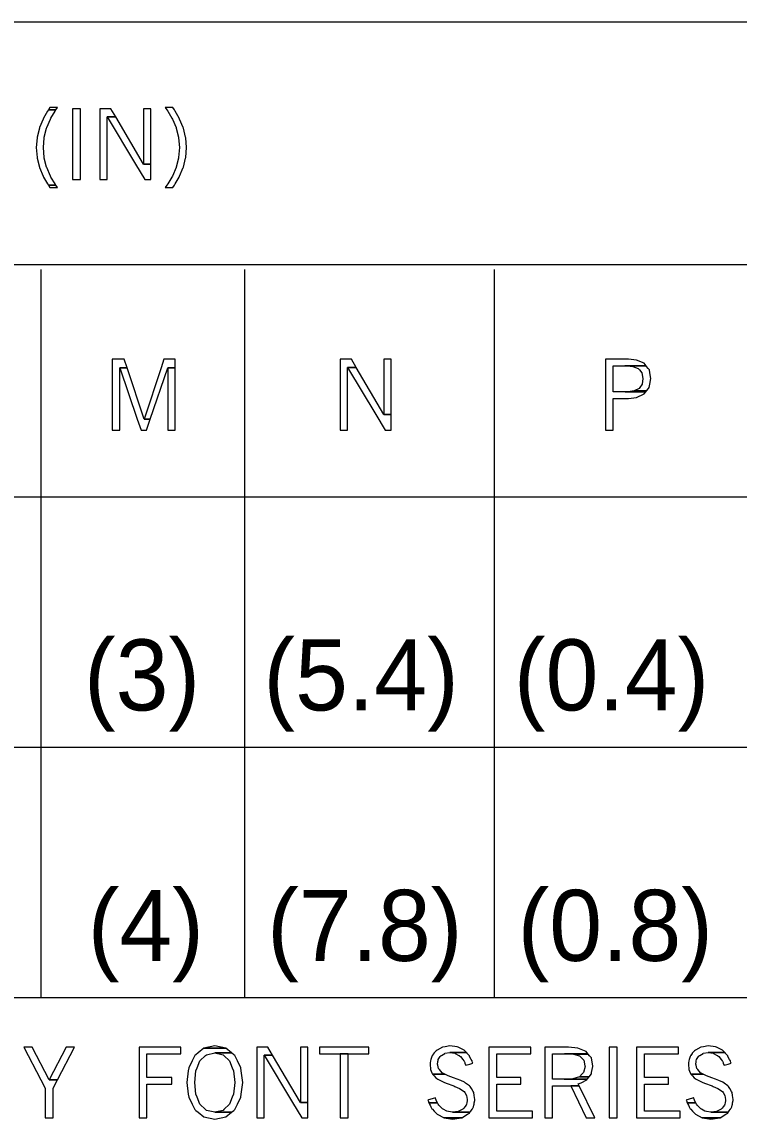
# Model space of a CAD drawing. Extents: x 0.011 to 0.188, y 0.004 to 0.261.
# Drawn here: x 0.12175 to 0.14593, y 0.04972 to 0.0867 of the extents above; entities that cross this region are included whole.
import ezdxf

# ---------------------------------------------------------------- set-up
doc = ezdxf.new("R2010")
doc.units = 0
doc.layers.add('3', color=7, linetype='Continuous')

msp = doc.modelspace()

# ---------------------------------------------------------------- linework, layer by layer
at = {"layer": '3'}
for p, q in [((0.030682, 0.086699), (0.184743, 0.086699)), ((0.184743, 0.078509), (0.030682, 0.078509)), ((0.122391, 0.078357), (0.122391, 0.053813)), ((0.129254, 0.078357), (0.129254, 0.053813)), ((0.137666, 0.078357), (0.137666, 0.053813)), ((0.030615, 0.070697), (0.184743, 0.070697)), ((0.030682, 0.062255), (0.184743, 0.062255)), ((0.03075, 0.053813), (0.184743, 0.053813))]:
    msp.add_line(p, q, dxfattribs=at)
for points in [[(0.122616, 0.081242), (0.122643, 0.081197), (0.122897, 0.081197), (0.122867, 0.081242), (0.12273, 0.081472), (0.12273, 0.081472), (0.122711, 0.081504), (0.122587, 0.081788), (0.122581, 0.081809), (0.122504, 0.08211), (0.122502, 0.082131), (0.122477, 0.082465), (0.122502, 0.082798), (0.122504, 0.08282), (0.122581, 0.08312), (0.122587, 0.083141), (0.122711, 0.083425), (0.12273, 0.083457), (0.12273, 0.083457), (0.122867, 0.083687), (0.122897, 0.083732), (0.122643, 0.083732), (0.122616, 0.083687), (0.122479, 0.083457), (0.122465, 0.083425), (0.122346, 0.083141), (0.122338, 0.08312), (0.122266, 0.08282), (0.122261, 0.082798), (0.122236, 0.082465), (0.122261, 0.082131), (0.122266, 0.08211), (0.122338, 0.081809), (0.122346, 0.081788), (0.122465, 0.081504), (0.122479, 0.081472)], [(0.122694, 0.083811), (0.122643, 0.083732), (0.122897, 0.083732), (0.12295, 0.083811)], [(0.123454, 0.083773), (0.123454, 0.081386), (0.123721, 0.081386), (0.123721, 0.083773)], [(0.124378, 0.081909), (0.124378, 0.081386), (0.124626, 0.081386), (0.124626, 0.081909), (0.124626, 0.083498), (0.124914, 0.083498), (0.124752, 0.083773), (0.124378, 0.083773), (0.124378, 0.083498)], [(0.125848, 0.083773), (0.125848, 0.081909), (0.126096, 0.081909), (0.126096, 0.083773)], [(0.126637, 0.081197), (0.126584, 0.081118), (0.12684, 0.081118), (0.126891, 0.081197), (0.126918, 0.081242), (0.127055, 0.081472), (0.127068, 0.081504), (0.127188, 0.081788), (0.127196, 0.081809), (0.127268, 0.08211), (0.127273, 0.082131), (0.127298, 0.082465), (0.127273, 0.082798), (0.127268, 0.08282), (0.127196, 0.08312), (0.127188, 0.083141), (0.127068, 0.083425), (0.127055, 0.083457), (0.126918, 0.083687), (0.126891, 0.083732), (0.12684, 0.083811), (0.126584, 0.083811), (0.126637, 0.083732), (0.126667, 0.083687), (0.126804, 0.083457), (0.126823, 0.083425), (0.126947, 0.083141), (0.126952, 0.08312), (0.12703, 0.08282), (0.127031, 0.082798), (0.127057, 0.082465), (0.127031, 0.082131), (0.12703, 0.08211), (0.126952, 0.081809), (0.126947, 0.081788), (0.126823, 0.081504), (0.126804, 0.081472), (0.126667, 0.081242)], [(0.125578, 0.081909), (0.125891, 0.081386), (0.126096, 0.081386), (0.126096, 0.081909), (0.125848, 0.081909), (0.124914, 0.083498), (0.124626, 0.083498)], [(0.122643, 0.081197), (0.122694, 0.081118), (0.12295, 0.081118), (0.122897, 0.081197)], [(0.124796, 0.073314), (0.124796, 0.072944), (0.12505, 0.072944), (0.12505, 0.073314), (0.12505, 0.075044), (0.125295, 0.075044), (0.125201, 0.075331), (0.124796, 0.075331), (0.124796, 0.075044)], [(0.126443, 0.075044), (0.125867, 0.073314), (0.126074, 0.073314), (0.126665, 0.075044), (0.126919, 0.075044), (0.126919, 0.075331), (0.126539, 0.075331)], [(0.132482, 0.073467), (0.132482, 0.072944), (0.13273, 0.072944), (0.13273, 0.073467), (0.13273, 0.075056), (0.133018, 0.075056), (0.132856, 0.075331), (0.132482, 0.075331), (0.132482, 0.075056)], [(0.133952, 0.075331), (0.133952, 0.073467), (0.1342, 0.073467), (0.1342, 0.075331)], [(0.141428, 0.07401), (0.141428, 0.072944), (0.141685, 0.072944), (0.141685, 0.07401), (0.142196, 0.07401), (0.142468, 0.074043), (0.142726, 0.074163), (0.142783, 0.074234), (0.141686, 0.074234), (0.141686, 0.074235), (0.141686, 0.074261), (0.141686, 0.074346), (0.141686, 0.074379), (0.141686, 0.074487), (0.141686, 0.074681), (0.141686, 0.074682), (0.141686, 0.074872), (0.141686, 0.074971), (0.141686, 0.075023), (0.141686, 0.07509), (0.141686, 0.075106), (0.141686, 0.075107), (0.142792, 0.075107), (0.142721, 0.075193), (0.142464, 0.075303), (0.142197, 0.075329), (0.14212, 0.075331), (0.141428, 0.075331), (0.141428, 0.075329), (0.141428, 0.075303), (0.141428, 0.075193), (0.141428, 0.075107), (0.141428, 0.075106), (0.141428, 0.07509), (0.141428, 0.075023), (0.141428, 0.074971), (0.141428, 0.074872), (0.141428, 0.074682), (0.141428, 0.074681), (0.141428, 0.074487), (0.141428, 0.074379), (0.141428, 0.074346), (0.141428, 0.074261), (0.141428, 0.074235), (0.141428, 0.074234), (0.141428, 0.074163), (0.141428, 0.074043)], [(0.142559, 0.074346), (0.142393, 0.074261), (0.142805, 0.074261), (0.142874, 0.074346), (0.1429, 0.074379), (0.14292, 0.074487), (0.142955, 0.074681), (0.142955, 0.074682), (0.142921, 0.074872), (0.142904, 0.074971), (0.142861, 0.075023), (0.142806, 0.07509), (0.142793, 0.075106), (0.142792, 0.075107), (0.14207, 0.075107), (0.142159, 0.075106), (0.142345, 0.07509), (0.142522, 0.075023), (0.142566, 0.074971), (0.142651, 0.074872), (0.142685, 0.074682), (0.142685, 0.074681), (0.142657, 0.074487), (0.142582, 0.074379)], [(0.125641, 0.073314), (0.125767, 0.072944), (0.125948, 0.072944), (0.126074, 0.073314), (0.125867, 0.073314), (0.125296, 0.075044), (0.12505, 0.075044)], [(0.126665, 0.073314), (0.126665, 0.072944), (0.126919, 0.072944), (0.126919, 0.073314), (0.126919, 0.075044), (0.126665, 0.075044)], [(0.133682, 0.073467), (0.133996, 0.072944), (0.1342, 0.072944), (0.1342, 0.073467), (0.133952, 0.073467), (0.133018, 0.075056), (0.13273, 0.075056)], [(0.142183, 0.074235), (0.142089, 0.074234), (0.142783, 0.074234), (0.142784, 0.074235), (0.142805, 0.074261), (0.142393, 0.074261)], [(0.122539, 0.050766), (0.122539, 0.04976), (0.1228, 0.04976), (0.1228, 0.050766), (0.122945, 0.051043), (0.122669, 0.051043), (0.1221, 0.052147), (0.121812, 0.052147), (0.122393, 0.051043)], [(0.123238, 0.052147), (0.122669, 0.051043), (0.122945, 0.051043), (0.123526, 0.052147)], [(0.125704, 0.050901), (0.125704, 0.04976), (0.125966, 0.04976), (0.125966, 0.050901), (0.126808, 0.050901), (0.126808, 0.051126), (0.125966, 0.051126), (0.125966, 0.051921), (0.127102, 0.051921), (0.127102, 0.052147), (0.125704, 0.052147), (0.125704, 0.051921), (0.125704, 0.051126)], [(0.128251, 0.052185), (0.12788, 0.052108), (0.128622, 0.052108)], [(0.129667, 0.050283), (0.129667, 0.04976), (0.129915, 0.04976), (0.129915, 0.050283), (0.129915, 0.051872), (0.130203, 0.051872), (0.130041, 0.052147), (0.129667, 0.052147), (0.129667, 0.051872)], [(0.131137, 0.052147), (0.131137, 0.050283), (0.131385, 0.050283), (0.131385, 0.052147)], [(0.131779, 0.052147), (0.131779, 0.051917), (0.133442, 0.051917), (0.133442, 0.052147)], [(0.135571, 0.051283), (0.135594, 0.051233), (0.136009, 0.051233), (0.135912, 0.051283), (0.135823, 0.051388), (0.135791, 0.051427), (0.135768, 0.051533), (0.135759, 0.051574), (0.135764, 0.051602), (0.135767, 0.051624), (0.135776, 0.051674), (0.135777, 0.05168), (0.135785, 0.051728), (0.135854, 0.051834), (0.135867, 0.051852), (0.135878, 0.051859), (0.135894, 0.051869), (0.136004, 0.051936), (0.136006, 0.051937), (0.136177, 0.051964), (0.136735, 0.051964), (0.136677, 0.052026), (0.136657, 0.052047), (0.136456, 0.052143), (0.136425, 0.052158), (0.136171, 0.052185), (0.13617, 0.052185), (0.136013, 0.052158), (0.135924, 0.052143), (0.135752, 0.052047), (0.135714, 0.052026), (0.135663, 0.051964), (0.135641, 0.051937), (0.13564, 0.051936), (0.135585, 0.051869), (0.135577, 0.051859), (0.135575, 0.051852), (0.13557, 0.051834), (0.135538, 0.051728), (0.135524, 0.05168), (0.135523, 0.051674), (0.135508, 0.051624), (0.135509, 0.051602), (0.135511, 0.051574), (0.135514, 0.051533), (0.135521, 0.051427), (0.135524, 0.051388)], [(0.137494, 0.04999), (0.137494, 0.04976), (0.138957, 0.04976), (0.138957, 0.04999), (0.137756, 0.04999), (0.137756, 0.050903), (0.138567, 0.050903), (0.138567, 0.051124), (0.137756, 0.051124), (0.137756, 0.051921), (0.138901, 0.051921), (0.138901, 0.052147), (0.137494, 0.052147), (0.137494, 0.051921), (0.137494, 0.051124), (0.137494, 0.050903)], [(0.139376, 0.050842), (0.139376, 0.04976), (0.139636, 0.04976), (0.139636, 0.050842), (0.140533, 0.050842), (0.140503, 0.050904), (0.140605, 0.05094), (0.140792, 0.051046), (0.140806, 0.051064), (0.139636, 0.051064), (0.139636, 0.051067), (0.139636, 0.051082), (0.139636, 0.05115), (0.139636, 0.051246), (0.139636, 0.05129), (0.139636, 0.051494), (0.139636, 0.051514), (0.139636, 0.051705), (0.139636, 0.051782), (0.139636, 0.051852), (0.139636, 0.051911), (0.139636, 0.051922), (0.139636, 0.051924), (0.140828, 0.051924), (0.140768, 0.051997), (0.140492, 0.052116), (0.140175, 0.052144), (0.140046, 0.052147), (0.139376, 0.052147), (0.139376, 0.052144), (0.139376, 0.052116), (0.139376, 0.051997), (0.139376, 0.051924), (0.139376, 0.051922), (0.139376, 0.051911), (0.139376, 0.051852), (0.139376, 0.051782), (0.139376, 0.051705), (0.139376, 0.051514), (0.139376, 0.051494), (0.139376, 0.05129), (0.139376, 0.051246), (0.139376, 0.05115), (0.139376, 0.051082), (0.139376, 0.051067), (0.139376, 0.051064), (0.139376, 0.051046), (0.139376, 0.05094), (0.139376, 0.050904)], [(0.141548, 0.052147), (0.141548, 0.04976), (0.141816, 0.04976), (0.141816, 0.052147)], [(0.142472, 0.04999), (0.142472, 0.04976), (0.143935, 0.04976), (0.143935, 0.04999), (0.142734, 0.04999), (0.142734, 0.050903), (0.143546, 0.050903), (0.143546, 0.051124), (0.142734, 0.051124), (0.142734, 0.051921), (0.143879, 0.051921), (0.143879, 0.052147), (0.142472, 0.052147), (0.142472, 0.051921), (0.142472, 0.051124), (0.142472, 0.050903)], [(0.14428, 0.051283), (0.144302, 0.051233), (0.144717, 0.051233), (0.144621, 0.051283), (0.144532, 0.051388), (0.144499, 0.051427), (0.144476, 0.051533), (0.144467, 0.051574), (0.144472, 0.051602), (0.144475, 0.051624), (0.144484, 0.051674), (0.144485, 0.05168), (0.144493, 0.051728), (0.144563, 0.051834), (0.144575, 0.051852), (0.144586, 0.051859), (0.144602, 0.051869), (0.144712, 0.051936), (0.144715, 0.051937), (0.144885, 0.051964), (0.145444, 0.051964), (0.145385, 0.052026), (0.145365, 0.052047), (0.145165, 0.052143), (0.145133, 0.052158), (0.144879, 0.052185), (0.144879, 0.052185), (0.144722, 0.052158), (0.144632, 0.052143), (0.14446, 0.052047), (0.144422, 0.052026), (0.144372, 0.051964), (0.14435, 0.051937), (0.144349, 0.051936), (0.144294, 0.051869), (0.144286, 0.051859), (0.144283, 0.051852), (0.144278, 0.051834), (0.144247, 0.051728), (0.144233, 0.05168), (0.144231, 0.051674), (0.144216, 0.051624), (0.144217, 0.051602), (0.144219, 0.051574), (0.144222, 0.051533), (0.144229, 0.051427), (0.144232, 0.051388)], [(0.12788, 0.049798), (0.128251, 0.049721), (0.128622, 0.049798), (0.128811, 0.049951), (0.12825, 0.049951), (0.127968, 0.050015), (0.127939, 0.050043), (0.127747, 0.050227), (0.127657, 0.050455), (0.127617, 0.050556), (0.127575, 0.050953), (0.127617, 0.05135), (0.127657, 0.051451), (0.127747, 0.051679), (0.127939, 0.051863), (0.127968, 0.051891), (0.12825, 0.051956), (0.128811, 0.051956), (0.128622, 0.052108), (0.127879, 0.052108), (0.127691, 0.051956), (0.127611, 0.051891), (0.127577, 0.051863), (0.127485, 0.051679), (0.127373, 0.051451), (0.127359, 0.05135), (0.127308, 0.050953), (0.127359, 0.050556), (0.127373, 0.050455), (0.127485, 0.050227), (0.127577, 0.050043), (0.127611, 0.050015), (0.127691, 0.049951)], [(0.128532, 0.050015), (0.12825, 0.049951), (0.128811, 0.049951), (0.128891, 0.050015), (0.128891, 0.050015), (0.128925, 0.050043), (0.129016, 0.050227), (0.129129, 0.050455), (0.129142, 0.050556), (0.129194, 0.050953), (0.129142, 0.05135), (0.129129, 0.051451), (0.129016, 0.051679), (0.128925, 0.051863), (0.128891, 0.051891), (0.128891, 0.051891), (0.128811, 0.051956), (0.12825, 0.051956), (0.128532, 0.051891), (0.12856, 0.051863), (0.128753, 0.051679), (0.128843, 0.051451), (0.128883, 0.05135), (0.128925, 0.050953), (0.128883, 0.050556), (0.128843, 0.050455), (0.128753, 0.050227), (0.12856, 0.050043)], [(0.130867, 0.050283), (0.131181, 0.04976), (0.131385, 0.04976), (0.131385, 0.050283), (0.131137, 0.050283), (0.130203, 0.051872), (0.129915, 0.051872)], [(0.132475, 0.051917), (0.132475, 0.04976), (0.132745, 0.04976), (0.132745, 0.051917)], [(0.136696, 0.051574), (0.136712, 0.051533), (0.136853, 0.051574), (0.136949, 0.051602), (0.136942, 0.051624), (0.136927, 0.051674), (0.136925, 0.05168), (0.136899, 0.051728), (0.136844, 0.051834), (0.136834, 0.051852), (0.136831, 0.051859), (0.136826, 0.051869), (0.136762, 0.051936), (0.136761, 0.051937), (0.136735, 0.051964), (0.136176, 0.051964), (0.136348, 0.051937), (0.136358, 0.051936), (0.136477, 0.051869), (0.136495, 0.051859), (0.136507, 0.051852), (0.136539, 0.051834), (0.136617, 0.051728), (0.136653, 0.05168), (0.136658, 0.051674), (0.136677, 0.051624), (0.136685, 0.051602)], [(0.140154, 0.051922), (0.140342, 0.051911), (0.14084, 0.051911), (0.140831, 0.051922), (0.14083, 0.051922), (0.140828, 0.051924), (0.140043, 0.051924)], [(0.140642, 0.051246), (0.140542, 0.05115), (0.140873, 0.05115), (0.140947, 0.051246), (0.140956, 0.05129), (0.140995, 0.051494), (0.140999, 0.051514), (0.140962, 0.051705), (0.140947, 0.051782), (0.140889, 0.051852), (0.14084, 0.051911), (0.140341, 0.051911), (0.14055, 0.051852), (0.140616, 0.051782), (0.140691, 0.051705), (0.140728, 0.051514), (0.140732, 0.051494), (0.140687, 0.05129)], [(0.145404, 0.051574), (0.14542, 0.051533), (0.145561, 0.051574), (0.145658, 0.051602), (0.145651, 0.051624), (0.145635, 0.051674), (0.145633, 0.05168), (0.145608, 0.051728), (0.145552, 0.051834), (0.145543, 0.051852), (0.145539, 0.051859), (0.145534, 0.051869), (0.14547, 0.051936), (0.145469, 0.051937), (0.145444, 0.051964), (0.144885, 0.051964), (0.145057, 0.051937), (0.145067, 0.051936), (0.145185, 0.051869), (0.145203, 0.051859), (0.145215, 0.051852), (0.145248, 0.051834), (0.145326, 0.051728), (0.145361, 0.05168), (0.145366, 0.051674), (0.145385, 0.051624), (0.145394, 0.051602)], [(0.136459, 0.049974), (0.136267, 0.049949), (0.136855, 0.049949), (0.136871, 0.049974), (0.136878, 0.049984), (0.136924, 0.050054), (0.136934, 0.050069), (0.136934, 0.050069), (0.136946, 0.050087), (0.136978, 0.050136), (0.136988, 0.050191), (0.136994, 0.050224), (0.137, 0.050264), (0.137015, 0.050349), (0.137017, 0.050359), (0.137018, 0.050364), (0.137021, 0.050381), (0.137, 0.05052), (0.136986, 0.050616), (0.136967, 0.050648), (0.136904, 0.050751), (0.136862, 0.050819), (0.136839, 0.050836), (0.136709, 0.050931), (0.136665, 0.050963), (0.136541, 0.051016), (0.136422, 0.051068), (0.136301, 0.051111), (0.136119, 0.051177), (0.136009, 0.051233), (0.135594, 0.051233), (0.135646, 0.051177), (0.135707, 0.051111), (0.135775, 0.051068), (0.135856, 0.051016), (0.135978, 0.050963), (0.136051, 0.050931), (0.136309, 0.050836), (0.136348, 0.050819), (0.136506, 0.050751), (0.13666, 0.050648), (0.13668, 0.050616), (0.136742, 0.05052), (0.136763, 0.050381), (0.136765, 0.050364), (0.136764, 0.050359), (0.136762, 0.050349), (0.136744, 0.050264), (0.136736, 0.050224), (0.136729, 0.050191), (0.136684, 0.050136), (0.136645, 0.050087), (0.136629, 0.050069), (0.136618, 0.050054), (0.136479, 0.049984)], [(0.14012, 0.051067), (0.140034, 0.051064), (0.140806, 0.051064), (0.140809, 0.051067), (0.140821, 0.051082), (0.140873, 0.05115), (0.140542, 0.05115), (0.140324, 0.051082)], [(0.145168, 0.049974), (0.144976, 0.049949), (0.145563, 0.049949), (0.14558, 0.049974), (0.145586, 0.049984), (0.145633, 0.050054), (0.145642, 0.050069), (0.145642, 0.050069), (0.145654, 0.050087), (0.145687, 0.050136), (0.145696, 0.050191), (0.145702, 0.050224), (0.145709, 0.050264), (0.145724, 0.050349), (0.145725, 0.050359), (0.145726, 0.050364), (0.14573, 0.050381), (0.145709, 0.05052), (0.145694, 0.050616), (0.145675, 0.050648), (0.145612, 0.050751), (0.145571, 0.050819), (0.145547, 0.050836), (0.145418, 0.050931), (0.145374, 0.050963), (0.145249, 0.051016), (0.14513, 0.051068), (0.145009, 0.051111), (0.144828, 0.051177), (0.144717, 0.051233), (0.144302, 0.051233), (0.144354, 0.051177), (0.144415, 0.051111), (0.144484, 0.051068), (0.144564, 0.051016), (0.144686, 0.050963), (0.14476, 0.050931), (0.145018, 0.050836), (0.145056, 0.050819), (0.145215, 0.050751), (0.145368, 0.050648), (0.145389, 0.050616), (0.14545, 0.05052), (0.145471, 0.050381), (0.145474, 0.050364), (0.145473, 0.050359), (0.14547, 0.050349), (0.145453, 0.050264), (0.145444, 0.050224), (0.145438, 0.050191), (0.145393, 0.050136), (0.145353, 0.050087), (0.145338, 0.050069), (0.145326, 0.050054), (0.145187, 0.049984)], [(0.140249, 0.050842), (0.140772, 0.04976), (0.141063, 0.04976), (0.140533, 0.050842)], [(0.135441, 0.050349), (0.135472, 0.050264), (0.13576, 0.050264), (0.135716, 0.050349), (0.135713, 0.050359), (0.135711, 0.050364), (0.135706, 0.050381), (0.135705, 0.050381), (0.135687, 0.050439), (0.135687, 0.050439), (0.135506, 0.050381), (0.135454, 0.050364), (0.135437, 0.050359)], [(0.144149, 0.050349), (0.14418, 0.050264), (0.144468, 0.050264), (0.144425, 0.050349), (0.144421, 0.050359), (0.14442, 0.050364), (0.144414, 0.050381), (0.144414, 0.050381), (0.144396, 0.050439), (0.144395, 0.050439), (0.144215, 0.050381), (0.144162, 0.050364), (0.144146, 0.050359)], [(0.135749, 0.049882), (0.135979, 0.049765), (0.136575, 0.049765), (0.136773, 0.049882), (0.136835, 0.049918), (0.136855, 0.049949), (0.136267, 0.049949), (0.136125, 0.049974), (0.136125, 0.049974), (0.136069, 0.049984), (0.135954, 0.050054), (0.135931, 0.050069), (0.135901, 0.050087), (0.135858, 0.050136), (0.135809, 0.050191), (0.135809, 0.050191), (0.13578, 0.050224), (0.13576, 0.050264), (0.135471, 0.050264), (0.135492, 0.050224), (0.135509, 0.050191), (0.135538, 0.050136), (0.135563, 0.050087), (0.135573, 0.050069), (0.135586, 0.050054), (0.135652, 0.049984), (0.135662, 0.049974), (0.135686, 0.049949), (0.135714, 0.049918)], [(0.144457, 0.049882), (0.144687, 0.049765), (0.145283, 0.049765), (0.145481, 0.049882), (0.145543, 0.049918), (0.145563, 0.049949), (0.144976, 0.049949), (0.144833, 0.049974), (0.144833, 0.049974), (0.144777, 0.049984), (0.144663, 0.050054), (0.144639, 0.050069), (0.144609, 0.050087), (0.144566, 0.050136), (0.144518, 0.050191), (0.144517, 0.050191), (0.144489, 0.050224), (0.144468, 0.050264), (0.14418, 0.050264), (0.1442, 0.050224), (0.144218, 0.050191), (0.144246, 0.050136), (0.144271, 0.050087), (0.144281, 0.050069), (0.144294, 0.050054), (0.144361, 0.049984), (0.14437, 0.049974), (0.144394, 0.049949), (0.144423, 0.049918)], [(0.135983, 0.049764), (0.136261, 0.049721), (0.136574, 0.049764), (0.136575, 0.049765), (0.135978, 0.049765)], [(0.144692, 0.049764), (0.144969, 0.049721), (0.145282, 0.049764), (0.145283, 0.049765), (0.144687, 0.049765)]]:
    msp.add_lwpolyline(points, close=True, dxfattribs=at)

# ---------------------------------------------------------------- texts
for s, p in [('(3)', (0.123845, 0.063494)), ('(5.4)', (0.129893, 0.063494)), ('(0.4)', (0.138335, 0.063494)), ('(4)', (0.123971, 0.055052)), ('(7.8)', (0.130019, 0.055052)), ('(0.8)', (0.138461, 0.055052))]:
    msp.add_text(s, height=0.0023943, dxfattribs=at).set_placement(p)

doc.saveas('drawing.dxf')
